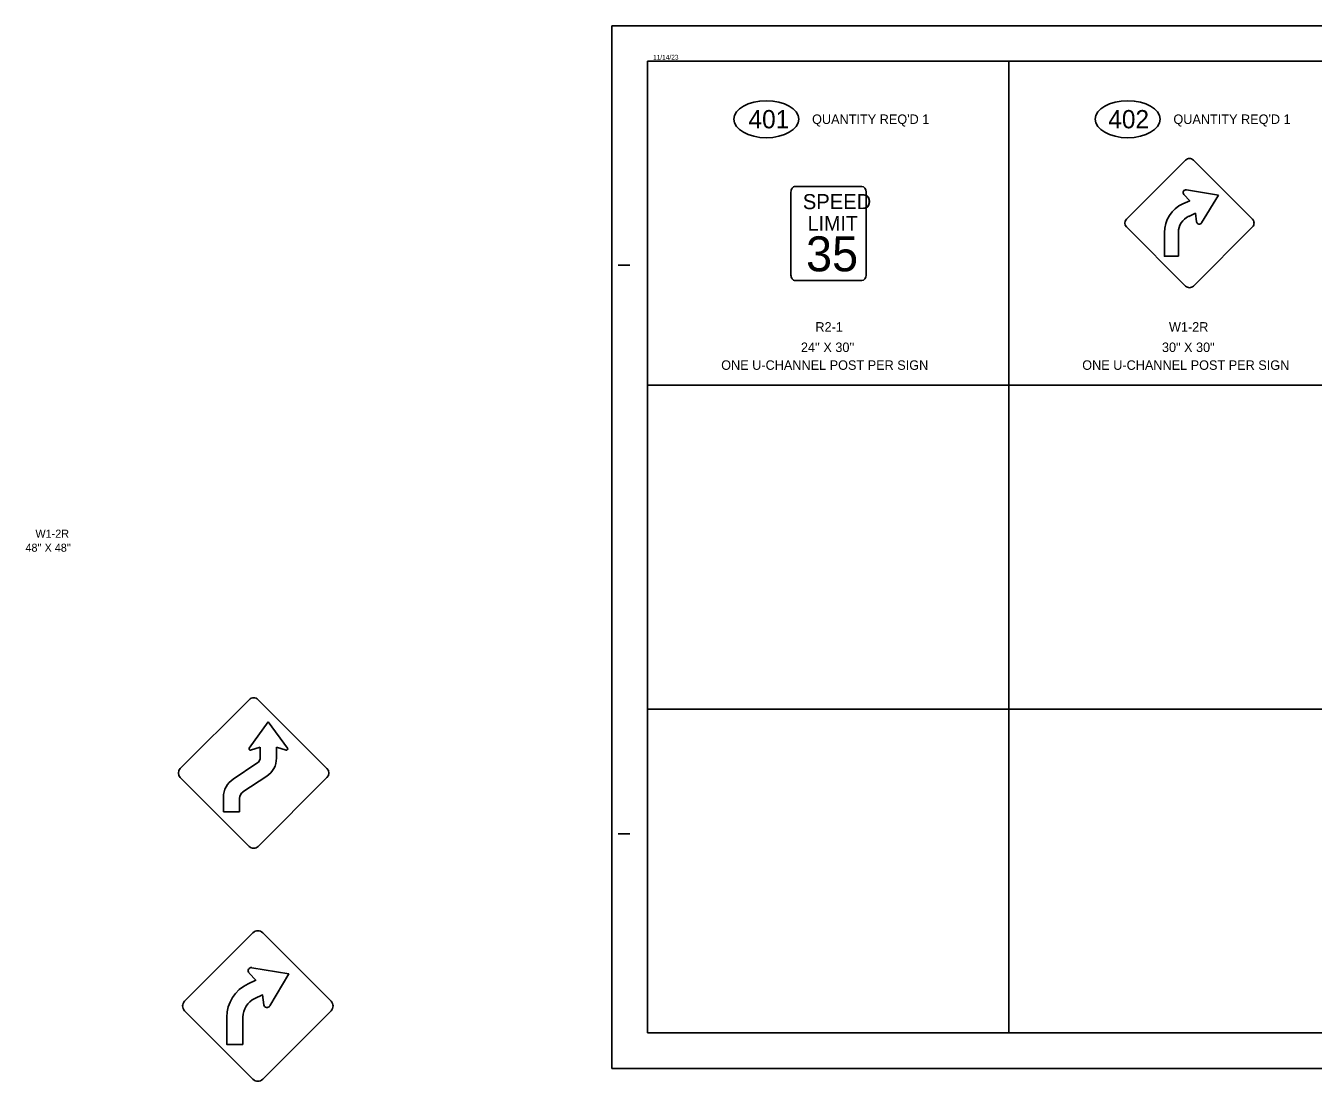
# Model space of a CAD drawing. Extents: x 1860868 to 1863318, y 1193312 to 1194425.
# Drawn here: x 1860868 to 1862226, y 1193312 to 1194425 of the extents above; entities that cross this region are included whole.
import ezdxf

# ---------------------------------------------------------------- set-up
doc = ezdxf.new("R2010")
doc.units = 0
for name, color, linetype in [('Default', 7, 'Continuous'), ('Level_1', 7, 'Continuous'), ('Old_Level_20', 7, 'Continuous'), ('Sheet Data Field CELL', 7, 'Continuous'), ('Sheet Plan CELL', 7, 'Continuous'), ('Sheet Sticker Incomplete CELL', 7, 'Continuous'), ('WS W1-2R CELL', 7, 'Continuous'), ('WZTC Sheet Plot Border', 7, 'Continuous')]:
    doc.layers.add(name, color=color, linetype=linetype)

msp = doc.modelspace()

# ---------------------------------------------------------------- linework, layer by layer
at = {"layer": 'Default'}
for q in [(1861523.9, 1193362.5), (1863048.9, 1194387.5)]:
    msp.add_line((1861523.9, 1194387.5), q, dxfattribs=at)
at = {"layer": 'Level_1'}
for p, q in [((1861905.2, 1194387.5), (1861905.1, 1193362.5)), ((1861523.9, 1194045.8), (1863048.9, 1194045.8)), ((1861523.9, 1193704.1), (1863048.9, 1193704.1))]:
    msp.add_line(p, q, dxfattribs=at)
at = {"layer": 'Old_Level_20'}
for p, q in [((1861486.4, 1193325), (1861486.4, 1194425)), ((1861486.4, 1194425), (1863186.4, 1194425)), ((1861486.4, 1193325), (1863186.4, 1193325))]:
    msp.add_line(p, q, dxfattribs=at)
at = {"layer": 'Sheet Data Field CELL'}
for p, q in [((1861103.7, 1193662.8), (1861123.9, 1193690.5)), ((1861123.9, 1193690.5), (1861144.2, 1193662.8)), ((1861115.4, 1193664.1), (1861105.1, 1193660.8)), ((1861115.4, 1193653.4), (1861115.4, 1193664.1)), ((1861142.8, 1193660.8), (1861132.5, 1193664.1)), ((1861132.5, 1193664.1), (1861132.5, 1193652.4)), ((1861086.8, 1193630.3), (1861111.9, 1193646.9)), ((1861122.2, 1193633.3), (1861097, 1193616.7)), ((1861185.8, 1193631.8), (1861113.2, 1193559.2)), ((1861076.7, 1193595.8), (1861076.7, 1193611.4)), ((1861093.6, 1193610.1), (1861093.6, 1193595.8)), ((1861093.6, 1193595.8), (1861076.7, 1193595.8)), ((1861107.7, 1193468.1), (1861035.6, 1193396)), ((1861190.1, 1193396), (1861118, 1193468.1)), ((1861035.6, 1193385.7), (1861107.7, 1193313.6)), ((1861097.1, 1193350.4), (1861097.1, 1193379)), ((1861097.1, 1193350.4), (1861097.1, 1193379)), ((1861097.1, 1193350.4), (1861097.1, 1193379)), ((1861118, 1193313.6), (1861190.1, 1193385.7))]:
    msp.add_line(p, q, dxfattribs=at)
for points in [[(1861675.3, 1194162), (1861675.3, 1194249.6)], [(1861679.9, 1194255.4), (1861714.9, 1194255.4)], [(1861714.9, 1194255.4), (1861749.9, 1194255.4)], [(1861754.5, 1194249.6), (1861754.5, 1194162)], [(1861714.9, 1194156.3), (1861679.9, 1194156.3)], [(1861749.9, 1194156.3), (1861714.9, 1194156.3)], [(1861031, 1193641.4), (1861103.6, 1193714)], [(1861113.2, 1193714), (1861185.8, 1193641.4)], [(1861103.6, 1193559.2), (1861031, 1193631.8)], [(1861103.6, 1193425.7), (1861110.7, 1193418), (1861102.5, 1193414.2)], [(1861103.6, 1193425.7), (1861110.7, 1193418), (1861102.5, 1193414.2)], [(1861103.6, 1193425.7), (1861110.7, 1193418), (1861102.5, 1193414.2)], [(1861125.5, 1193390.9), (1861145.5, 1193424.8), (1861106.6, 1193431.3)], [(1861125.5, 1193390.9), (1861145.5, 1193424.8), (1861106.6, 1193431.3)], [(1861125.5, 1193390.9), (1861145.5, 1193424.8), (1861106.6, 1193431.3)], [(1861109.7, 1193398.8), (1861117.8, 1193402.6), (1861119.2, 1193392.2)], [(1861109.7, 1193398.8), (1861117.8, 1193402.6), (1861119.2, 1193392.2)], [(1861109.7, 1193398.8), (1861117.8, 1193402.6), (1861119.2, 1193392.2)], [(1861080.1, 1193379), (1861080.1, 1193350.4), (1861097.1, 1193350.4)], [(1861080.1, 1193379), (1861080.1, 1193350.4), (1861097.1, 1193350.4)], [(1861080.1, 1193379), (1861080.1, 1193350.4), (1861097.1, 1193350.4)]]:
    msp.add_lwpolyline(points, dxfattribs=at)
for centre, start, end in [((1861112.8, 1193463), 45, 135), ((1861040.7, 1193390.9), 135, 225), ((1861184.9, 1193390.9), 315, 45), ((1861112.8, 1193318.8), 225, 315)]:
    msp.add_arc(centre, 7.27, start, end, dxfattribs=at)
for centre in [(1861649.3, 1194326.4), (1862030.6, 1194326.4)]:
    msp.add_ellipse(centre, major_axis=(-34.2, 0), ratio=0.571429, dxfattribs=at)
for centre, major_axis, ratio, start_param, end_param in [((1861679.9, 1194249.6), (0, 5.78), 0.800002, 6.282958, 7.853982), ((1861749.9, 1194249.6), (0, 5.78), 0.800002, 4.712389, 6.283185), ((1861679.9, 1194162), (0, 5.78), 0.800002, 1.570796, 3.141593), ((1861749.9, 1194162), (0, -5.78), 0.800002, 0, 1.570796), ((1861108.4, 1193709.2), (-6.78, 0), 0.999996, 4.712275, 5.497787), ((1861108.4, 1193709.2), (-6.78, 0), 0.999996, 3.926763, 4.712275), ((1861104.8, 1193662.1), (1.29, 0), 0.999996, 2.511665, 4.931771), ((1861107.6, 1193653.5), (7.79, 0), 0.999996, 5.298427, 6.283185), ((1861109.7, 1193652.3), (22.8, 0), 0.999996, 5.298425, 6.283185), ((1861143.1, 1193662.1), (1.29, 0), 0.999996, 4.493007, 6.913113), ((1861035.8, 1193636.6), (-6.78, 0), 0.999996, 5.497787, 7.068583), ((1861181, 1193636.6), (6.78, 0), 0.999996, 5.497787, 7.068583), ((1861099.4, 1193611.3), (-22.8, 0), 0.999996, 5.298425, 6.283185), ((1861101.4, 1193610.1), (-7.79, 0), 0.999996, 5.298422, 6.283185), ((1861108.4, 1193564), (6.78, 0), 0.999996, 3.926991, 4.712389), ((1861108.4, 1193564), (6.78, 0), 0.999996, 4.712389, 5.497787), ((1861106.1, 1193428), (0, 3.39), 0.999989, 6.117174, 8.596418), ((1861106.1, 1193428), (0, 3.39), 0.999989, 6.117174, 8.596418), ((1861106.1, 1193428), (0, 3.39), 0.999989, 6.117174, 8.596418), ((1861118.9, 1193379), (0, 38.8), 0.999989, 0.435241, 1.570796), ((1861118.9, 1193379), (0, 38.8), 0.999989, 0.435241, 1.570796), ((1861118.9, 1193379), (0, 38.8), 0.999989, 0.435241, 1.570796), ((1861118.9, 1193379), (0, -21.8), 0.999989, 3.576834, 4.712389), ((1861118.9, 1193379), (0, -21.8), 0.999989, 3.576834, 4.712389), ((1861118.9, 1193379), (0, -21.8), 0.999989, 3.576834, 4.712389), ((1861122.5, 1193392.6), (0, -3.39), 0.999989, 4.840436, 7.319679), ((1861122.5, 1193392.6), (0, -3.39), 0.999989, 4.840436, 7.319679), ((1861122.5, 1193392.6), (0, -3.39), 0.999989, 4.840436, 7.319679)]:
    msp.add_ellipse(centre, major_axis=major_axis, ratio=ratio, start_param=start_param, end_param=end_param, dxfattribs=at)
at = {"layer": 'Sheet Plan CELL'}
for p, q in [((1861523.9, 1193362.5), (1861523.9, 1194387.5)), ((1863148.9, 1194387.5), (1861523.9, 1194387.5)), ((1861553.9, 1194395), (1861553.9, 1194395)), ((1861492.9, 1194172.5), (1861505.4, 1194172.5)), ((1861492.9, 1193572.5), (1861505.4, 1193572.5)), ((1861523.9, 1193362.5), (1863148.9, 1193362.5))]:
    msp.add_line(p, q, dxfattribs=at)
at = {"layer": 'Sheet Sticker Incomplete CELL'}
msp.add_line((1861486.4, 1193325), (1861486.4, 1193325), dxfattribs=at)
at = {"layer": 'WS W1-2R CELL'}
for p, q in [((1862092.5, 1194251.9), (1862126.2, 1194246.2)), ((1862092.5, 1194251.9), (1862092.5, 1194251.9)), ((1862126.2, 1194246.2), (1862108.6, 1194217.1))]:
    msp.add_line(p, q, dxfattribs=at)
for points in [[(1862029.3, 1194220.9), (1862091.7, 1194283.3)], [(1862099.9, 1194283.3), (1862162.2, 1194220.9)], [(1862088.9, 1194237.2), (1862096, 1194240.4), (1862089.9, 1194247)], [(1862103.2, 1194218.2), (1862102.1, 1194227.1), (1862095.1, 1194223.9)], [(1862091.7, 1194150.4), (1862029.3, 1194212.7)], [(1862162.2, 1194212.7), (1862099.9, 1194150.4)], [(1862084, 1194206.8), (1862084, 1194182), (1862069.3, 1194181.9), (1862069.3, 1194206.8)]]:
    msp.add_lwpolyline(points, dxfattribs=at)
for centre, major_axis, ratio, start_param, end_param in [((1862095.8, 1194279.2), (0, 5.82), 0.999959, 6.283071, 7.068583), ((1862095.8, 1194279.2), (0, 5.82), 0.999959, 5.497559, 6.283071), ((1862092, 1194249), (-2.95, 0), 0.99403, 4.544825, 7.025321), ((1862103, 1194206.8), (33.7, 0), 0.99403, 2.002303, 3.142125), ((1862033.4, 1194216.8), (0, 5.82), 0.999959, 0.785398, 2.356194), ((1862103, 1194206.8), (19, 0), 0.99403, 2.002303, 3.142125), ((1862158.1, 1194216.8), (0, 5.82), 0.999959, 3.92699, 5.497787), ((1862106.1, 1194218.6), (-2.95, 0), 0.99403, 0.120762, 2.601373), ((1862095.8, 1194154.5), (0, -5.82), 0.999959, 5.497787, 6.283185), ((1862095.8, 1194154.5), (0, -5.82), 0.999959, 6.283185, 7.068583)]:
    msp.add_ellipse(centre, major_axis=major_axis, ratio=ratio, start_param=start_param, end_param=end_param, dxfattribs=at)
at = {"layer": 'WZTC Sheet Plot Border'}
msp.add_lwpolyline([(1861486.4, 1194425), (1863186.4, 1194425), (1863186.4, 1193325), (1861486.4, 1193325)], close=True, dxfattribs=at)

# ---------------------------------------------------------------- texts
at = {"layer": 'Level_1'}
for s, p in [("QUANTITY REQ'D 1", (1861697.6, 1194321.4)), ("QUANTITY REQ'D 1", (1862078.8, 1194321.4)), ('R2-1', (1861701.1, 1194102.3)), ('W1-2R', (1862074.1, 1194102.3)), ("24'' X 30''", (1861685.8, 1194080.8)), ('30" X 30"', (1862066.7, 1194080.8)), ('ONE U-CHANNEL POST PER SIGN', (1861601.7, 1194062)), ('ONE U-CHANNEL POST PER SIGN', (1861982.6, 1194062))]:
    msp.add_text(s, height=10, dxfattribs=at).set_placement(p)
at = {"layer": 'Sheet Data Field CELL'}
for s, p in [('401', (1861630.5, 1194316.8)), ('402', (1862010.1, 1194316.8))]:
    msp.add_text(s, height=19.28, rotation=359.9659, dxfattribs=at).set_placement(p)
for s, height, p in [('SPEED', 15.92, (1861687.8, 1194231.5)), ('LIMIT', 15.5, (1861692.9, 1194208.9)), ('35', 36.93, (1861691.2, 1194165.9))]:
    msp.add_text(s, height=height, dxfattribs=at).set_placement(p)
at = {"layer": 'Sheet Plan CELL'}
msp.add_text('11/14/23', height=5, rotation=0, dxfattribs=at).set_placement((1861529.8, 1194389.3))
at = {"layer": 'WS W1-2R CELL'}
for s, height, p in [('W1-2R', 8.52, (1860878.2, 1193884.9)), ("48'' X 48''", 8.515, (1860867.7, 1193870.1))]:
    msp.add_text(s, height=height, rotation=360, dxfattribs=at).set_placement(p)

doc.saveas('drawing.dxf')
